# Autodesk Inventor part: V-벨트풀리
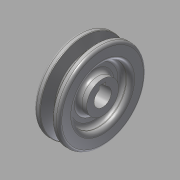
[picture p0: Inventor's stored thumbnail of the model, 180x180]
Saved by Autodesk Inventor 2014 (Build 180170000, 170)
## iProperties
Created: 2015-12
Part Number: V-벨트풀리
Material: 강철, 연강
Document SubType Name: Modeling
Designer: mduedu
Density: 7.86 g/cm^3
Appearance: 강철
Author: mduedu
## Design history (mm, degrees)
sketch "스케치1"
  geometry: L1 (-9.5, 0)-(9.5, 0); L2 (-9.5, 0)-(-9.5, 32.7); L3 (-9.5, 32.7)-(-4.825, 32.7); L4 (-4.825, 32.7)-(-2.074, 23.7); L5 (-2.074, 23.7)-(0, 23.7); L6 (0, 0)-(0, 23.7); L7 (9.5, 0)-(9.5, 32.7); L8 (9.5, 32.7)-(4.825, 32.7); L9 (4.825, 32.7)-(2.074, 23.7); L10 (2.074, 23.7)-(0, 23.7); L11 (-4, 30)-(4, 30); 3 further points
  constraints: 22 end point, 3 coincident, 3 perpendicular, 3 symmetric about line, 2 parallel, 2 point on line, 1 horizontal, 1 midpoint, 1 vertical alignment
  dimensions: "d0" = 19 distance between parallel lines of L7 L2; "d2" = 6.3 distance between parallel lines of L10 L11; "d3" = 34 deg angle of L9 L4; "d4" = 2.7 distance between parallel lines of L11 L8; "d5" = 60 diameter of L11 L1; "d6" = 8 distance of L11.end L11.start
revolve "회전1" sketch "스케치1" stored, may be unused: angle "d7" = 90 deg
sketch "스케치2"
  geometry: C1 r 21 at (0, 0); C2 r 12 at (0, 0); 1 further point
  constraints: 2 centre point, 2 coincident
  dimensions: "d8" = 42 diameter of C1; "d10" = 24 diameter of C2
extrude "돌출1" cut sketch "스케치2" distance "d11" = 6.5; taper "d12" = 0 deg
fillet "모깎기1" dims "d13" = 1, "d14" = 0.5, "d15" = 2
fillet "모깎기2" dims "d16" = 3
fillet "모깎기3" dims "d17" = 3
hole "구멍1" diameter "d20" = 13; stored, may be unused: countersink angle "d24" = 90 deg, drill point angle "d26" = 118 deg; dims "d18" = 10, "d19" = 10, "d21" = 6, "d22" = 4, "d23" = 2, "d25" = 8
sketch "스케치3"
  geometry: L1 (-2.5, 0)-(2.5, 0); L2 (2.5, 0)-(2.5, 8.8); L3 (2.5, 8.8)-(-2.5, 8.8); L4 (-2.5, 8.8)-(-2.5, 0); 2 further points
  constraints: 8 end point, 2 parallel, 1 coincident, 1 horizontal, 1 midpoint, 1 perpendicular
  dimensions: "d27" = 8.8 distance of L1.end L2.end; "d29" = 5 distance of L2.end L3.end
extrude "돌출2" cut sketch "스케치3" stored distance "d30" = 6.5; taper "d31" = 0 deg
node "솔리드1"
mirror "대칭1"
